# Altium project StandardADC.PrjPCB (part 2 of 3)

## Sheet StdADC05.SchDoc
size B
Used 2 times, as channels FPGA1, FPGA2. Parts and nets are listed once, with the designators drawn on the sheet.
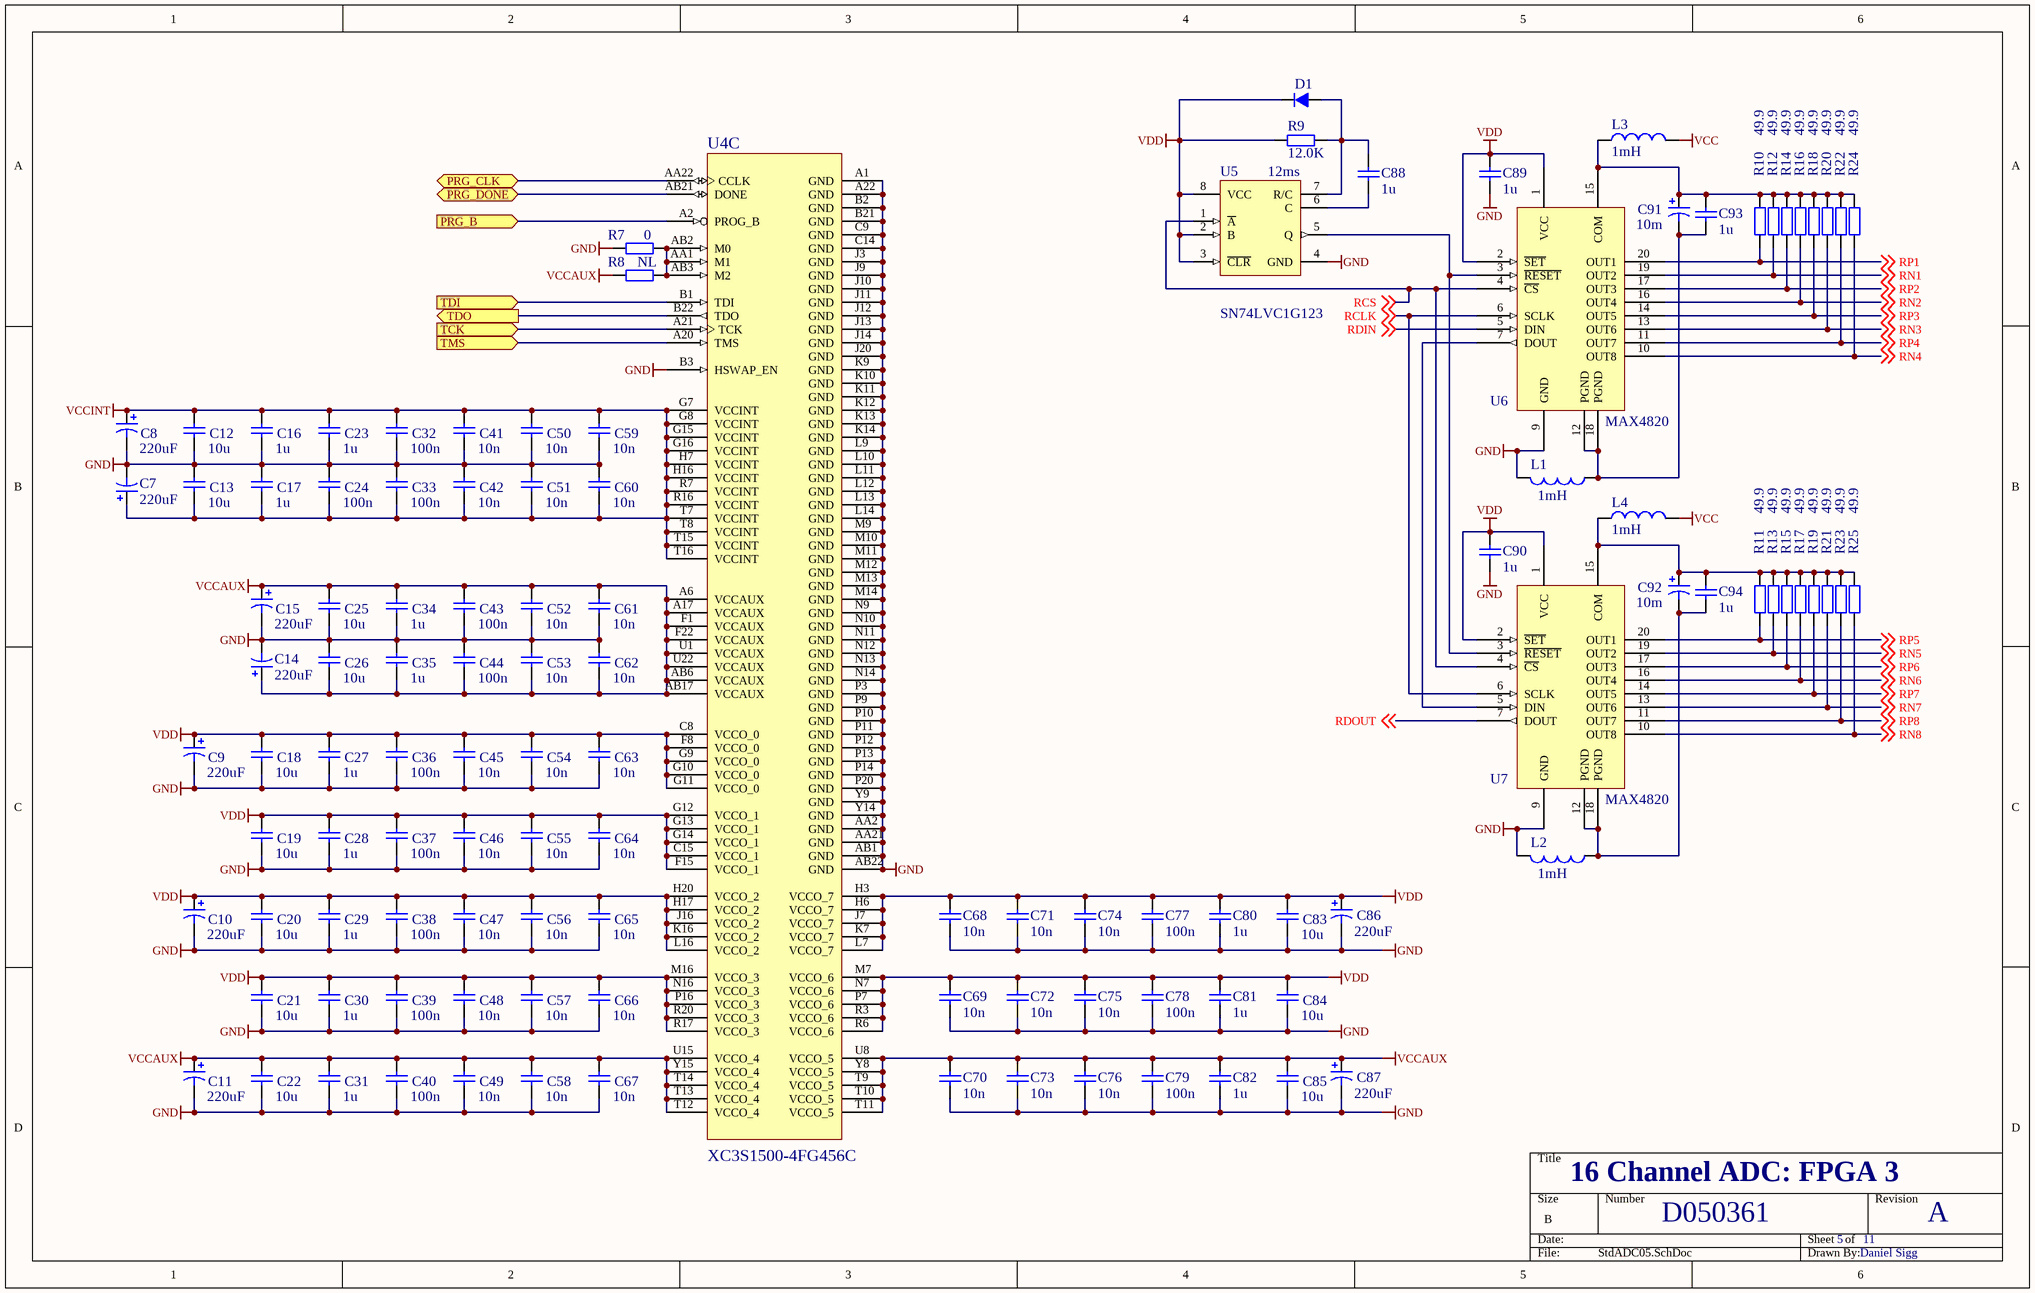
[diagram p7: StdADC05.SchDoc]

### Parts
C7  220uF  [D]
C8  220uF  [D]
C9  220uF  [D]
C10  220uF  [D]
C11  220uF  [D]
C12  value 10u  [CC2012-0805]  (hidden comment: Cap)
C13  value 10u  [CC2012-0805]  (hidden comment: Cap)
C14  220uF  [D]
C15  220uF  [D]
C16  value 1u  [CC1608-0603]  (hidden comment: Cap)
C17  value 1u  [CC1608-0603]  (hidden comment: Cap)
C18  value 10u  [CC2012-0805]  (hidden comment: Cap)
C19  value 10u  [CC2012-0805]  (hidden comment: Cap)
C20  value 10u  [CC2012-0805]  (hidden comment: Cap)
C21  value 10u  [CC2012-0805]  (hidden comment: Cap)
C22  value 10u  [CC2012-0805]  (hidden comment: Cap)
C23  value 1u  [CC1608-0603]  (hidden comment: Cap)
C24  value 100n  [CC1608-0603]  (hidden comment: Cap)
C25  value 10u  [CC2012-0805]  (hidden comment: Cap)
C26  value 10u  [CC2012-0805]  (hidden comment: Cap)
C27  value 1u  [CC1608-0603]  (hidden comment: Cap)
C28  value 1u  [CC1608-0603]  (hidden comment: Cap)
C29  value 1u  [CC1608-0603]  (hidden comment: Cap)
C30  value 1u  [CC1608-0603]  (hidden comment: Cap)
C31  value 1u  [CC1608-0603]  (hidden comment: Cap)
C32  value 100n  [CC1608-0603]  (hidden comment: Cap)
C33  value 100n  [CC1608-0603]  (hidden comment: Cap)
C34  value 1u  [CC1608-0603]  (hidden comment: Cap)
C35  value 1u  [CC1608-0603]  (hidden comment: Cap)
C36  value 100n  [CC1608-0603]  (hidden comment: Cap)
C37  value 100n  [CC1608-0603]  (hidden comment: Cap)
C38  value 100n  [CC1608-0603]  (hidden comment: Cap)
C39  value 100n  [CC1608-0603]  (hidden comment: Cap)
C40  value 100n  [CC1608-0603]  (hidden comment: Cap)
C41  value 10n  [CC1005-0402]  (hidden comment: Cap)
C42  value 10n  [CC1005-0402]  (hidden comment: Cap)
C43  value 100n  [CC1608-0603]  (hidden comment: Cap)
C44  value 100n  [CC1608-0603]  (hidden comment: Cap)
C45  value 10n  [CC1005-0402]  (hidden comment: Cap)
C46  value 10n  [CC1005-0402]  (hidden comment: Cap)
C47  value 10n  [CC1005-0402]  (hidden comment: Cap)
C48  value 10n  [CC1005-0402]  (hidden comment: Cap)
C49  value 10n  [CC1005-0402]  (hidden comment: Cap)
C50  value 10n  [CC1005-0402]  (hidden comment: Cap)
C51  value 10n  [CC1005-0402]  (hidden comment: Cap)
C52  value 10n  [CC1005-0402]  (hidden comment: Cap)
C53  value 10n  [CC1005-0402]  (hidden comment: Cap)
C54  value 10n  [CC1005-0402]  (hidden comment: Cap)
C55  value 10n  [CC1005-0402]  (hidden comment: Cap)
C56  value 10n  [CC1005-0402]  (hidden comment: Cap)
C57  value 10n  [CC1005-0402]  (hidden comment: Cap)
C58  value 10n  [CC1005-0402]  (hidden comment: Cap)
C59  value 10n  [CC1005-0402]  (hidden comment: Cap)
C60  value 10n  [CC1005-0402]  (hidden comment: Cap)
C61  value 10n  [CC1005-0402]  (hidden comment: Cap)
C62  value 10n  [CC1005-0402]  (hidden comment: Cap)
C63  value 10n  [CC1005-0402]  (hidden comment: Cap)
C64  value 10n  [CC1005-0402]  (hidden comment: Cap)
C65  value 10n  [CC1005-0402]  (hidden comment: Cap)
C66  value 10n  [CC1005-0402]  (hidden comment: Cap)
C67  value 10n  [CC1005-0402]  (hidden comment: Cap)
C68  value 10n  [CC1005-0402]  (hidden comment: Cap)
C69  value 10n  [CC1005-0402]  (hidden comment: Cap)
C70  value 10n  [CC1005-0402]  (hidden comment: Cap)
C71  value 10n  [CC1005-0402]  (hidden comment: Cap)
C72  value 10n  [CC1005-0402]  (hidden comment: Cap)
C73  value 10n  [CC1005-0402]  (hidden comment: Cap)
C74  value 10n  [CC1005-0402]  (hidden comment: Cap)
C75  value 10n  [CC1005-0402]  (hidden comment: Cap)
C76  value 10n  [CC1005-0402]  (hidden comment: Cap)
C77  value 100n  [CC1608-0603]  (hidden comment: Cap)
C78  value 100n  [CC1608-0603]  (hidden comment: Cap)
C79  value 100n  [CC1608-0603]  (hidden comment: Cap)
C80  value 1u  [CC1608-0603]  (hidden comment: Cap)
C81  value 1u  [CC1608-0603]  (hidden comment: Cap)
C82  value 1u  [CC1608-0603]  (hidden comment: Cap)
C83  value 10u  [CC2012-0805]  (hidden comment: Cap)
C84  value 10u  [CC2012-0805]  (hidden comment: Cap)
C85  value 10u  [CC2012-0805]  (hidden comment: Cap)
C86  220uF  [D]
C87  220uF  [D]
C88  value 1u  [CC1608-0603]  (hidden comment: Cap)
C89  value 1u  [CC1608-0603]  (hidden comment: Cap)
C90  value 1u  [CC1608-0603]  (hidden comment: Cap)
C91  10m  [RB7.6-15]
C92  10m  [RB7.6-15]
C93  value 1u  [CC1608-0603]  (hidden comment: Cap)
C94  value 1u  [CC1608-0603]  (hidden comment: Cap)
D1  diode  [SO-G3/C2.25]  (value not drawn)
L1  1mH  [CC4532-1812]
L2  1mH  [CC4532-1812]
L3  1mH  [CC4532-1812]
L4  1mH  [CC4532-1812]
R7  0  [CR2012-0805]
R8  NL  [CR2012-0805]
R9  12.0K  [CR2012-0805]
R10  49.9  [CR2012-0805]
R11  49.9  [CR2012-0805]
R12  49.9  [CR2012-0805]
R13  49.9  [CR2012-0805]
R14  49.9  [CR2012-0805]
R15  49.9  [CR2012-0805]
R16  49.9  [CR2012-0805]
R17  49.9  [CR2012-0805]
R18  49.9  [CR2012-0805]
R19  49.9  [CR2012-0805]
R20  49.9  [CR2012-0805]
R21  49.9  [CR2012-0805]
R22  49.9  [CR2012-0805]
R23  49.9  [CR2012-0805]
R24  49.9  [CR2012-0805]
R25  49.9  [CR2012-0805]
U4  XC3S1500-4FG456C  [FG456]  (part C of 3)
U5  SN74LVC1G123  Pulse width: 12ms  [SSO-G8/SM8]
U6  MAX4820  [TSSOP20]
U7  MAX4820  [TSSOP20]

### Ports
PRG_B (in), PRG_CLK (bidir), PRG_DONE (bidir), TCK (in), TDI (in), TDO (out), TMS (in)

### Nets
GND: C7.2 C8.2 C9.2 C10.2 C11.2 C12.2 C13.1 C14.2 C15.2 C16.2 C17.1 C18.2 C19.2 C20.2 C21.2 C22.2 C23.2 C24.1 C25.2 C26.1 C27.2 C28.2 C29.2 C30.2 C31.2 C32.2 C33.1 C34.2 C35.1 C36.2 C37.2 C38.2 C39.2 C40.2 C41.2 C42.1 C43.2 C44.1 C45.2 C46.2 C47.2 C48.2 C49.2 C50.2 C51.1 C52.2 C53.1 C54.2 C55.2 C56.2 C57.2 C58.2 C59.2 C60.1 C61.2 C62.1 C63.2 C64.2 C65.2 C66.2 C67.2 C68.2 C69.2 C70.2 C71.2 C72.2 C73.2 C74.2 C75.2 C76.2 C77.2 C78.2 C79.2 C80.2 C81.2 C82.2 C83.2 C84.2 C85.2 C86.2 C87.2 C89.1 C90.1 L1.2 L2.2 R7.2 U4.A1(GND) U4.A22(GND) U4.AA2(GND) U4.AA21(GND) U4.AB1(GND) U4.AB22(GND) U4.B2(GND) U4.B3(HSWAP_EN) U4.B21(GND) U4.C9(GND) U4.C14(GND) U4.J3(GND) U4.J9(GND) U4.J10(GND) U4.J11(GND) U4.J12(GND) U4.J13(GND) U4.J14(GND) U4.J20(GND) U4.K9(GND) U4.K10(GND) U4.K11(GND) U4.K12(GND) U4.K13(GND) U4.K14(GND) U4.L9(GND) U4.L10(GND) U4.L11(GND) U4.L12(GND) U4.L13(GND) U4.L14(GND) U4.M9(GND) U4.M10(GND) U4.M11(GND) U4.M12(GND) U4.M13(GND) U4.M14(GND) U4.N9(GND) U4.N10(GND) U4.N11(GND) U4.N12(GND) U4.N13(GND) U4.N14(GND) U4.P3(GND) U4.P9(GND) U4.P10(GND) U4.P11(GND) U4.P12(GND) U4.P13(GND) U4.P14(GND) U4.P20(GND) U4.Y9(GND) U4.Y14(GND) U5.4(GND) U6.9(GND) U7.9(GND)
VCC: L3.2 L4.2
VCCAUX: C11.1 C14.1 C15.1 C22.1 C25.1 C26.2 C31.1 C34.1 C35.2 C40.1 C43.1 C44.2 C49.1 C52.1 C53.2 C58.1 C61.1 C62.2 C67.1 C70.1 C73.1 C76.1 C79.1 C82.1 C85.1 C87.1 R8.2 U4.A6(VCCAUX) U4.A17(VCCAUX) U4.AB6(VCCAUX) U4.AB17(VCCAUX) U4.F1(VCCAUX) U4.F22(VCCAUX) U4.T9(VCCO_5) U4.T10(VCCO_5) U4.T11(VCCO_5) U4.T12(VCCO_4) U4.T13(VCCO_4) U4.T14(VCCO_4) U4.U1(VCCAUX) U4.U8(VCCO_5) U4.U15(VCCO_4) U4.U22(VCCAUX) U4.Y8(VCCO_5) U4.Y15(VCCO_4)
VCCINT: C7.1 C8.1 C12.1 C13.2 C16.1 C17.2 C23.1 C24.2 C32.1 C33.2 C41.1 C42.2 C50.1 C51.2 C59.1 C60.2 U4.G7(VCCINT) U4.G8(VCCINT) U4.G15(VCCINT) U4.G16(VCCINT) U4.H7(VCCINT) U4.H16(VCCINT) U4.R7(VCCINT) U4.R16(VCCINT) U4.T7(VCCINT) U4.T8(VCCINT) U4.T15(VCCINT) U4.T16(VCCINT)
VDD: C9.1 C10.1 C18.1 C19.1 C20.1 C21.1 C27.1 C28.1 C29.1 C30.1 C36.1 C37.1 C38.1 C39.1 C45.1 C46.1 C47.1 C48.1 C54.1 C55.1 C56.1 C57.1 C63.1 C64.1 C65.1 C66.1 C68.1 C69.1 C71.1 C72.1 C74.1 C75.1 C77.1 C78.1 C80.1 C81.1 C83.1 C84.1 C86.1 C89.2 C90.2 D1.3(K) R9.1 U4.C8(VCCO_0) U4.C15(VCCO_1) U4.F8(VCCO_0) U4.F15(VCCO_1) U4.G9(VCCO_0) U4.G10(VCCO_0) U4.G11(VCCO_0) U4.G12(VCCO_1) U4.G13(VCCO_1) U4.G14(VCCO_1) U4.H3(VCCO_7) U4.H6(VCCO_7) U4.H17(VCCO_2) U4.H20(VCCO_2) U4.J7(VCCO_7) U4.J16(VCCO_2) U4.K7(VCCO_7) U4.K16(VCCO_2) U4.L7(VCCO_7) U4.L16(VCCO_2) U4.M7(VCCO_6) U4.M16(VCCO_3) U4.N7(VCCO_6) U4.N16(VCCO_3) U4.P7(VCCO_6) U4.P16(VCCO_3) U4.R3(VCCO_6) U4.R6(VCCO_6) U4.R17(VCCO_3) U4.R20(VCCO_3) U5.2(B) U5.3(~{CLR}) U5.8(VCC) U6.1(VCC) U6.2(~{SET}) U7.1(VCC) U7.2(~{SET})
PRG_B: U4.A2(PROG_B) ; port PRG_B
PRG_CLK: U4.AA22(CCLK) ; port PRG_CLK
PRG_DONE: U4.AB21(DONE) ; port PRG_DONE
RCLK: U6.6(SCLK) U7.6(SCLK) ; off-sheet RCLK
RCS: U5.1(~{A}) U6.4(~{CS}) U7.4(~{CS}) ; off-sheet RCS
RDIN: U6.5(DIN) ; off-sheet RDIN
RDOUT: U7.7(DOUT) ; off-sheet RDOUT
RN1: R12.2 U6.19(OUT2) ; off-sheet RN1
RN2: R16.2 U6.16(OUT4) ; off-sheet RN2
RN3: R20.2 U6.13(OUT6) ; off-sheet RN3
RN4: R24.2 U6.10(OUT8) ; off-sheet RN4
RN5: R13.2 U7.19(OUT2) ; off-sheet RN5
RN6: R17.2 U7.16(OUT4) ; off-sheet RN6
RN7: R21.2 U7.13(OUT6) ; off-sheet RN7
RN8: R25.2 U7.10(OUT8) ; off-sheet RN8
RP1: R10.2 U6.20(OUT1) ; off-sheet RP1
RP2: R14.2 U6.17(OUT3) ; off-sheet RP2
RP3: R18.2 U6.14(OUT5) ; off-sheet RP3
RP4: R22.2 U6.11(OUT7) ; off-sheet RP4
RP5: R11.2 U7.20(OUT1) ; off-sheet RP5
RP6: R15.2 U7.17(OUT3) ; off-sheet RP6
RP7: R19.2 U7.14(OUT5) ; off-sheet RP7
RP8: R23.2 U7.11(OUT7) ; off-sheet RP8
TCK: U4.A21(TCK) ; port TCK
TDI: U4.B1(TDI) ; port TDI
TDO: U4.B22(TDO) ; port TDO
TMS: U4.A20(TMS) ; port TMS
NetC88_1: C88.1 U5.6(C)
NetC88_2: C88.2 D1.1(A) R9.2 U5.7(R/C)
NetC91_1: C91.1 C93.2 L3.1 R10.1 R12.1 R14.1 R16.1 R18.1 R20.1 R22.1 R24.1 U6.15(COM)
NetC91_2: C91.2 C93.1 L1.1 U6.12(PGND) U6.18(PGND)
NetC92_1: C92.1 C94.2 L4.1 R11.1 R13.1 R15.1 R17.1 R19.1 R21.1 R23.1 R25.1 U7.15(COM)
NetC92_2: C92.2 C94.1 L2.1 U7.12(PGND) U7.18(PGND)
NetR7_1: R7.1 R8.1 U4.AA1(M1) U4.AB2(M0) U4.AB3(M2)
NetU5_5: U5.5(Q) U6.3(~{RESET}) U7.3(~{RESET})
NetU6_7: U6.7(DOUT) U7.5(DIN)

Not connected (* = marked no-connect by the designer): D1 2; U6 8(NC); U7 8(NC)

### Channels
FPGA1: designators C7=C7A C8=C8A C9=C9A C10=C10A C11=C11A C12=C12A C13=C13A C14=C14A C15=C15A C16=C16A C17=C17A C18=C18A C19=C19A C20=C20A C21=C21A C22=C22A C23=C23A C24=C24A C25=C25A C26=C26A C27=C27A C28=C28A C29=C29A C30=C30A C31=C31A C32=C32A C33=C33A C34=C34A C35=C35A C36=C36A C37=C37A C38=C38A C39=C39A C40=C40A C41=C41A C42=C42A C43=C43A C44=C44A C45=C45A C46=C46A C47=C47A C48=C48A C49=C49A C50=C50A C51=C51A C52=C52A C53=C53A C54=C54A C55=C55A C56=C56A C57=C57A C58=C58A C59=C59A C60=C60A C61=C61A C62=C62A C63=C63A C64=C64A C65=C65A C66=C66A C67=C67A C68=C68A C69=C69A C70=C70A C71=C71A C72=C72A C73=C73A C74=C74A C75=C75A C76=C76A C77=C77A C78=C78A C79=C79A C80=C80A C81=C81A C82=C82A C83=C83A C84=C84A C85=C85A C86=C86A C87=C87A C88=C88A C89=C89A C90=C90A C91=C91A C92=C92A C93=C93A C94=C94A D1=D1A L1=L1A L2=L2A L3=L3A L4=L4A R7=R7A R8=R8A R9=R9A R10=R10A R11=R11A R12=R12A R13=R13A R14=R14A R15=R15A R16=R16A R17=R17A R18=R18A R19=R19A R20=R20A R21=R21A R22=R22A R23=R23A R24=R24A R25=R25A U4=U4A#3 U5=U5A U6=U6A U7=U7A; ports PRG_B=NetU4A#3_A2 PRG_CLK=NetU4A#3_AA22 PRG_DONE=NetU4A#3_AB21 TCK=NetU4A#3_A21 TDI=NetU4A#3_B1 TDO=NetU4A#3_B22 TMS=NetU4A#3_A20
FPGA2: designators C7=C7B C8=C8B C9=C9B C10=C10B C11=C11B C12=C12B C13=C13B C14=C14B C15=C15B C16=C16B C17=C17B C18=C18B C19=C19B C20=C20B C21=C21B C22=C22B C23=C23B C24=C24B C25=C25B C26=C26B C27=C27B C28=C28B C29=C29B C30=C30B C31=C31B C32=C32B C33=C33B C34=C34B C35=C35B C36=C36B C37=C37B C38=C38B C39=C39B C40=C40B C41=C41B C42=C42B C43=C43B C44=C44B C45=C45B C46=C46B C47=C47B C48=C48B C49=C49B C50=C50B C51=C51B C52=C52B C53=C53B C54=C54B C55=C55B C56=C56B C57=C57B C58=C58B C59=C59B C60=C60B C61=C61B C62=C62B C63=C63B C64=C64B C65=C65B C66=C66B C67=C67B C68=C68B C69=C69B C70=C70B C71=C71B C72=C72B C73=C73B C74=C74B C75=C75B C76=C76B C77=C77B C78=C78B C79=C79B C80=C80B C81=C81B C82=C82B C83=C83B C84=C84B C85=C85B C86=C86B C87=C87B C88=C88B C89=C89B C90=C90B C91=C91B C92=C92B C93=C93B C94=C94B D1=D1B L1=L1B L2=L2B L3=L3B L4=L4B R7=R7B R8=R8B R9=R9B R10=R10B R11=R11B R12=R12B R13=R13B R14=R14B R15=R15B R16=R16B R17=R17B R18=R18B R19=R19B R20=R20B R21=R21B R22=R22B R23=R23B R24=R24B R25=R25B U4=U4B#3 U5=U5B U6=U6B U7=U7B; ports PRG_B=NetU4A#3_A2 PRG_CLK=NetU4A#3_AA22 PRG_DONE=NetU4A#3_AB21 TCK=NetU4A#3_A21 TDI=NetU4A#3_B22 TDO=NetU4B#3_B22 TMS=NetU4A#3_A20

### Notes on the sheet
- 16 Channel ADC: FPGA 3
- D050361
- 5
- 11
- A
- Daniel Sigg

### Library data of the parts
C7-C11 C14 C15 C86 C87 = T494D: Solid Tantalum Chip Capacitor, Standard T494 Series - Low ESR, Industrial Grade; Part Number: PCE3603CT-ND
C12 C13 C16-C85 C88-C90 C93 C94 = Cap: Capacitor; Manufacturer: Generic Components; Part Number: 399-1254-1-ND; Class I: Passive
C91 C92 = Cap Pol1: Polarized Capacitor (Radial)
D1 = DIODE_SOT23: Single diode in SOT23 package; Part Number: BAT400D-FDICT-ND
L1-L4 = Inductor: Code_IEC: 1005
R7 R8 = Res2: Resistor
R9-R25 = Res2: Resistor; Tolerance: 1%
U4 = XC3S1500-4FG456C: Spartan-3 1.2V FPGA, 333 User I/Os, 456-ball FBGA, Standard Performance, Commercial Grade; PackageDocument: ver1.1, Apr-2001
U5 = SN74LVC1G123: Single retriggerable monostable multivibrator
U6 U7 = MAX4820: 8 channel relay driver, serial interface

## Sheet StdADC10.SchDoc
size B
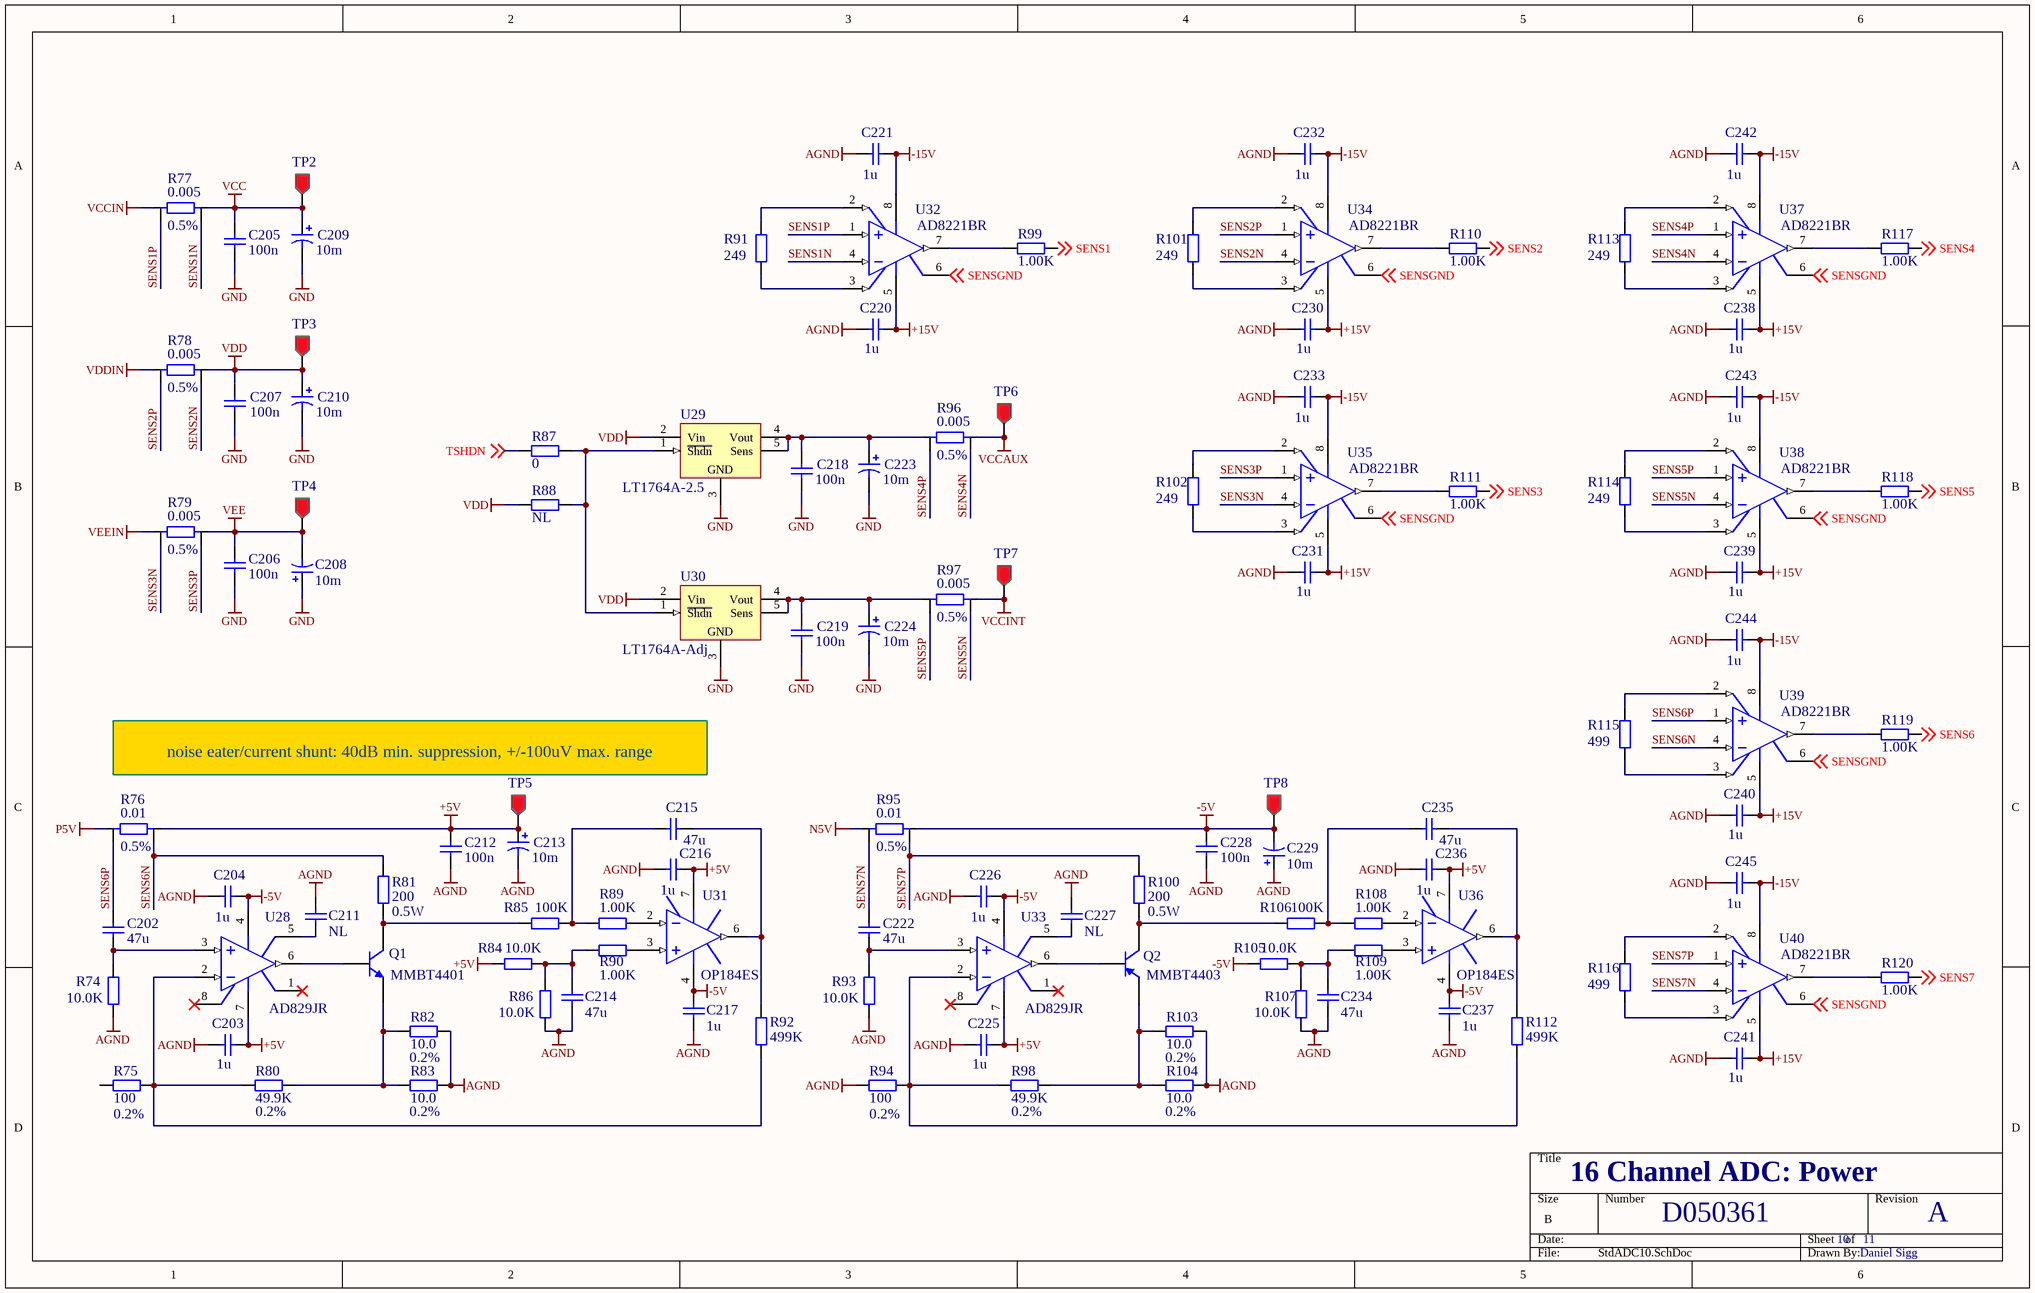
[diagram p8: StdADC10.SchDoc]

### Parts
C202  47u  [CC3225-1210]
C203  1u  [CC2012-0805]
C204  1u  [CC2012-0805]
C205  100n  [CC2012-0805]
C206  100n  [CC2012-0805]
C207  100n  [CC2012-0805]
C208  10m  [RB7.6-15]
C209  10m  [RB7.6-15]
C210  10m  [RB7.6-15]
C211  NL  [CC2012-0805]
C212  100n  [CC1005-0402]
C213  10m  [RB7.6-15]
C214  47u  [CC3225-1210]
C215  47u  [CC3225-1210]
C216  1u  [CC2012-0805]
C217  1u  [CC2012-0805]
C218  100n  [CC2012-0805]
C219  100n  [CC2012-0805]
C220  1u  [CC2012-0805]
C221  1u  [CC2012-0805]
C222  47u  [CC3225-1210]
C223  10m  [RB7.6-15]
C224  10m  [RB7.6-15]
C225  1u  [CC2012-0805]
C226  1u  [CC2012-0805]
C227  NL  [CC2012-0805]
C228  100n  [CC1005-0402]
C229  10m  [RB7.6-15]
C230  1u  [CC2012-0805]
C231  1u  [CC2012-0805]
C232  1u  [CC2012-0805]
C233  1u  [CC2012-0805]
C234  47u  [CC3225-1210]
C235  47u  [CC3225-1210]
C236  1u  [CC2012-0805]
C237  1u  [CC2012-0805]
C238  1u  [CC2012-0805]
C239  1u  [CC2012-0805]
C240  1u  [CC2012-0805]
C241  1u  [CC2012-0805]
C242  1u  [CC2012-0805]
C243  1u  [CC2012-0805]
C244  1u  [CC2012-0805]
C245  1u  [CC2012-0805]
Q1  MMBT4401  [SOT-23A]
Q2  MMBT4403  [SOT-23A]
R74  10.0K  [CR2012-0805]
R75  Tolerance: 0.2%  [CR2012-0805]  (hidden comment: 100)
R76  Tolerance: 0.5%  [RW10862-4325]  (hidden comment: 0.01)
R77  Tolerance: 0.5%  [RW10862-4325]  (hidden comment: 0.005)
R78  Tolerance: 0.5%  [RW10862-4325]  (hidden comment: 0.005)
R79  Tolerance: 0.5%  [RW10862-4325]  (hidden comment: 0.005)
R80  Tolerance: 0.2%  [CR2012-0805]  (hidden comment: 49.9K)
R81  Power: 0.5W  [CR5025-2010]  (hidden comment: 200)
R82  Tolerance: 0.2%  [CR2012-0805]  (hidden comment: 10.0)
R83  Tolerance: 0.2%  [CR2012-0805]  (hidden comment: 10.0)
R84  10.0K  [CR2012-0805]
R85  100K  [CR2012-0805]
R86  10.0K  [CR2012-0805]
R87  0  [CR2012-0805]
R88  NL  [CR2012-0805]
R89  1.00K  [CR2012-0805]
R90  1.00K  [CR2012-0805]
R91  249  [CR2012-0805]
R92  499K  [CR2012-0805]
R93  10.0K  [CR2012-0805]
R94  Tolerance: 0.2%  [CR2012-0805]  (hidden comment: 100)
R95  Tolerance: 0.5%  [RW10862-4325]  (hidden comment: 0.01)
R96  Tolerance: 0.5%  [RW10862-4325]  (hidden comment: 0.005)
R97  Tolerance: 0.5%  [RW10862-4325]  (hidden comment: 0.005)
R98  Tolerance: 0.2%  [CR2012-0805]  (hidden comment: 49.9K)
R99  1.00K  [CR2012-0805]
R100  Power: 0.5W  [CR5025-2010]  (hidden comment: 200)
R101  249  [CR2012-0805]
R102  249  [CR2012-0805]
R103  Tolerance: 0.2%  [CR2012-0805]  (hidden comment: 10.0)
R104  Tolerance: 0.2%  [CR2012-0805]  (hidden comment: 10.0)
R105  10.0K  [CR2012-0805]
R106  100K  [CR2012-0805]
R107  10.0K  [CR2012-0805]
R108  1.00K  [CR2012-0805]
R109  1.00K  [CR2012-0805]
R110  1.00K  [CR2012-0805]
R111  1.00K  [CR2012-0805]
R112  499K  [CR2012-0805]
R113  249  [CR2012-0805]
R114  249  [CR2012-0805]
R115  499  [CR2012-0805]
R116  499  [CR2012-0805]
R117  1.00K  [CR2012-0805]
R118  1.00K  [CR2012-0805]
R119  1.00K  [CR2012-0805]
R120  1.00K  [CR2012-0805]
TP2  Testpoint  [TP1]  (value not drawn)
TP3  Testpoint  [TP1]  (value not drawn)
TP4  Testpoint  [TP1]  (value not drawn)
TP5  Testpoint  [TP1]  (value not drawn)
TP6  Testpoint  [TP1]  (value not drawn)
TP7  Testpoint  [TP1]  (value not drawn)
TP8  Testpoint  [TP1]  (value not drawn)
U28  AD829JR  [R-8D]
U29  LT1764A-2.5  [TO-220-5B]
U30  LT1764A-Adj  [TO-220-5B]
U31  OP184ES  [R-8D]
U32  AD8221BR  [SO-G8]
U33  AD829JR  [R-8D]
U34  AD8221BR  [SO-G8]
U35  AD8221BR  [SO-G8]
U36  OP184ES  [R-8D]
U37  AD8221BR  [SO-G8]
U38  AD8221BR  [SO-G8]
U39  AD8221BR  [SO-G8]
U40  AD8221BR  [SO-G8]

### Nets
+5V: C203.1 C212.1 C213.1 C216.1 C225.1 C236.1 R76.4 R84.1 TP5.1 U28.7(V+) U31.7(V+) U33.7(V+) U36.7(V+)
+15V: C220.1 C230.1 C231.1 C238.1 C239.1 C240.1 C241.1 U32.5(V-) U34.5(V-) U35.5(V-) U37.5(V-) U38.5(V-) U39.5(V-) U40.5(V-)
-5V: C204.1 C217.1 C226.1 C228.1 C229.2 C237.1 R95.4 R105.1 TP8.1 U28.4(V-) U31.4(V-) U33.4(V-) U36.4(V-)
-15V: C221.1 C232.1 C233.1 C242.1 C243.1 C244.1 C245.1 U32.8(V+) U34.8(V+) U35.8(V+) U37.8(V+) U38.8(V+) U39.8(V+) U40.8(V+)
AGND: C203.2 C204.2 C211.2 C212.2 C213.2 C214.1 C216.2 C217.2 C220.2 C221.2 C225.2 C226.2 C227.2 C228.2 C229.1 C230.2 C231.2 C232.2 C233.2 C234.1 C236.2 C237.2 C238.2 C239.2 C240.2 C241.2 C242.2 C243.2 C244.2 C245.2 R74.2 R82.1 R83.1 R86.1 R93.2 R94.1 R103.1 R104.1 R107.1
GND: C205.2 C206.2 C207.2 C208.1 C209.2 C210.2 C218.2 C219.2 C223.2 C224.2 U29.3(GND) U30.3(GND)
N5V: R95.1
P5V: R76.1
VCC: C205.1 C209.1 R77.4 TP2.1
VCCAUX: R96.4 TP6.1
VCCIN: R77.1
VCCINT: R97.4 TP7.1
VDD: C207.1 C210.1 R78.4 R88.1 TP3.1 U29.2(Vin) U30.2(Vin)
VDDIN: R78.1
VEE: C206.1 C208.2 R79.4 TP4.1
VEEIN: R79.1
SENS1: R99.2 ; off-sheet SENS1
SENS1N: R77.3 U32.4(IN-)
SENS1P: R77.2 U32.1(IN+)
SENS2: R110.2 ; off-sheet SENS2
SENS2N: R78.3 U34.4(IN-)
SENS2P: R78.2 U34.1(IN+)
SENS3: R111.2 ; off-sheet SENS3
SENS3N: R79.2 U35.4(IN-)
SENS3P: R79.3 U35.1(IN+)
SENS4: R117.2 ; off-sheet SENS4
SENS4N: R96.3 U37.4(IN-)
SENS4P: R96.2 U37.1(IN+)
SENS5: R118.2 ; off-sheet SENS5
SENS5N: R97.3 U38.4(IN-)
SENS5P: R97.2 U38.1(IN+)
SENS6: R119.2 ; off-sheet SENS6
SENS6N: R76.3 R81.2 U39.4(IN-)
SENS6P: C202.1 R76.2 U39.1(IN+)
SENS7: R120.2 ; off-sheet SENS7
SENS7N: C222.1 R95.2 U40.4(IN-)
SENS7P: R95.3 R100.2 U40.1(IN+)
SENSGND: U32.6(REF) U34.6(REF) U35.6(REF) U37.6(REF) U38.6(REF) U39.6(REF) U40.6(REF) ; off-sheet SENSGND
TSHDN: R87.1 ; off-sheet TSHDN
NetC202_2: C202.2 R74.1 U28.3(IN+)
NetC211_1: C211.1 U28.5(C_COMP)
NetC214_2: C214.2 R84.2 R86.2 R90.1
NetC215_1: C215.1 R85.2 R89.1
NetC215_2: C215.2 R92.1 U31.6(OUT)
NetC218_1: C218.1 C223.1 R96.1 U29.4(Vout) U29.5(Sens)
NetC219_1: C219.1 C224.1 R97.1 U30.4(Vout) U30.5(Sens)
NetC222_2: C222.2 R93.1 U33.3(IN+)
NetC227_1: C227.1 U33.5(C_COMP)
NetC234_2: C234.2 R105.2 R107.2 R109.1
NetC235_1: C235.1 R106.2 R108.1
NetC235_2: C235.2 R112.1 U36.6(OUT)
NetQ1_1: Q1.1(B) U28.6(OUT)
NetQ1_2: Q1.2(E) R80.1 R82.2 R83.2
NetQ1_3: Q1.3(C) R81.1 R85.1
NetQ2_1: Q2.1(B) U33.6(OUT)
NetQ2_2: Q2.2(E) R98.1 R103.2 R104.2
NetQ2_3: Q2.3(C) R100.1 R106.1
NetR75_2: R75.2 R80.2 R92.2 U28.2(IN-)
NetR87_2: R87.2 R88.2 U29.1(~{Shdn}) U30.1(~{Shdn})
NetR89_2: R89.2 U31.2(IN-)
NetR90_2: R90.2 U31.3(IN+)
NetR91_1: R91.1 U32.2(RG)
NetR91_2: R91.2 U32.3(RG)
NetR94_2: R94.2 R98.2 R112.2 U33.2(IN-)
NetR99_1: R99.1 U32.7(OUT)
NetR101_1: R101.1 U34.2(RG)
NetR101_2: R101.2 U34.3(RG)
NetR102_1: R102.1 U35.2(RG)
NetR102_2: R102.2 U35.3(RG)
NetR108_2: R108.2 U36.2(IN-)
NetR109_2: R109.2 U36.3(IN+)
NetR110_1: R110.1 U34.7(OUT)
NetR111_1: R111.1 U35.7(OUT)
NetR113_1: R113.1 U37.2(RG)
NetR113_2: R113.2 U37.3(RG)
NetR114_1: R114.1 U38.2(RG)
NetR114_2: R114.2 U38.3(RG)
NetR115_1: R115.1 U39.2(RG)
NetR115_2: R115.2 U39.3(RG)
NetR116_1: R116.1 U40.2(RG)
NetR116_2: R116.2 U40.3(RG)
NetR117_1: R117.1 U37.7(OUT)
NetR118_1: R118.1 U38.7(OUT)
NetR119_1: R119.1 U39.7(OUT)
NetR120_1: R120.1 U40.7(OUT)

Not connected (* = marked no-connect by the designer): R75 1; U28 1(OS_NUL)* 8(OS_NUL)*; U31 1(OS_NUL) 5(C_COMP) 8(OS_NUL); U33 1(OS_NUL)* 8(OS_NUL)*; U36 1(OS_NUL) 5(C_COMP) 8(OS_NUL)

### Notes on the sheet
- noise eater/current shunt: 40dB min. suppression, +/-100uV max. range
- 16 Channel ADC: Power
- D050361
- 10
- 11
- A
- Daniel Sigg

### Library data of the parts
C202-C207 C211 C212 C214-C222 C225-C228 C230-C245 = Cap Semi: Capacitor (Semiconductor SIM Model)
C208-C210 C213 C223 C224 C229 = Cap Pol1: Polarized Capacitor (Radial)
Q1 = BC817-40: NPN General Purpose Amplifier
Q2 = BC807-40: PNP General Purpose Amplifier
R74 R81-R93 R99-R120 = Res2: Resistor; Tolerance: 1%
R75 R80 R94 R98 = Res2: Resistor
R76-R79 R95-R97 = RW1S0CK: Four-Terminal Current Sense Resistor
TP2-TP8 = TP_POSITIVE
U28 U31 U33 U36 = AD829JR: High-Speed, Low-Noise Video Operational Amplifier; PackageDocument: 1998
U29 U30 = LT1764A: 5 Terminal positive LDO regulator
U32 U34 U35 U37-U40 = AD8221: Precision Instrumentation Amplifier

## Sheet StdADC11.SchDoc
size B
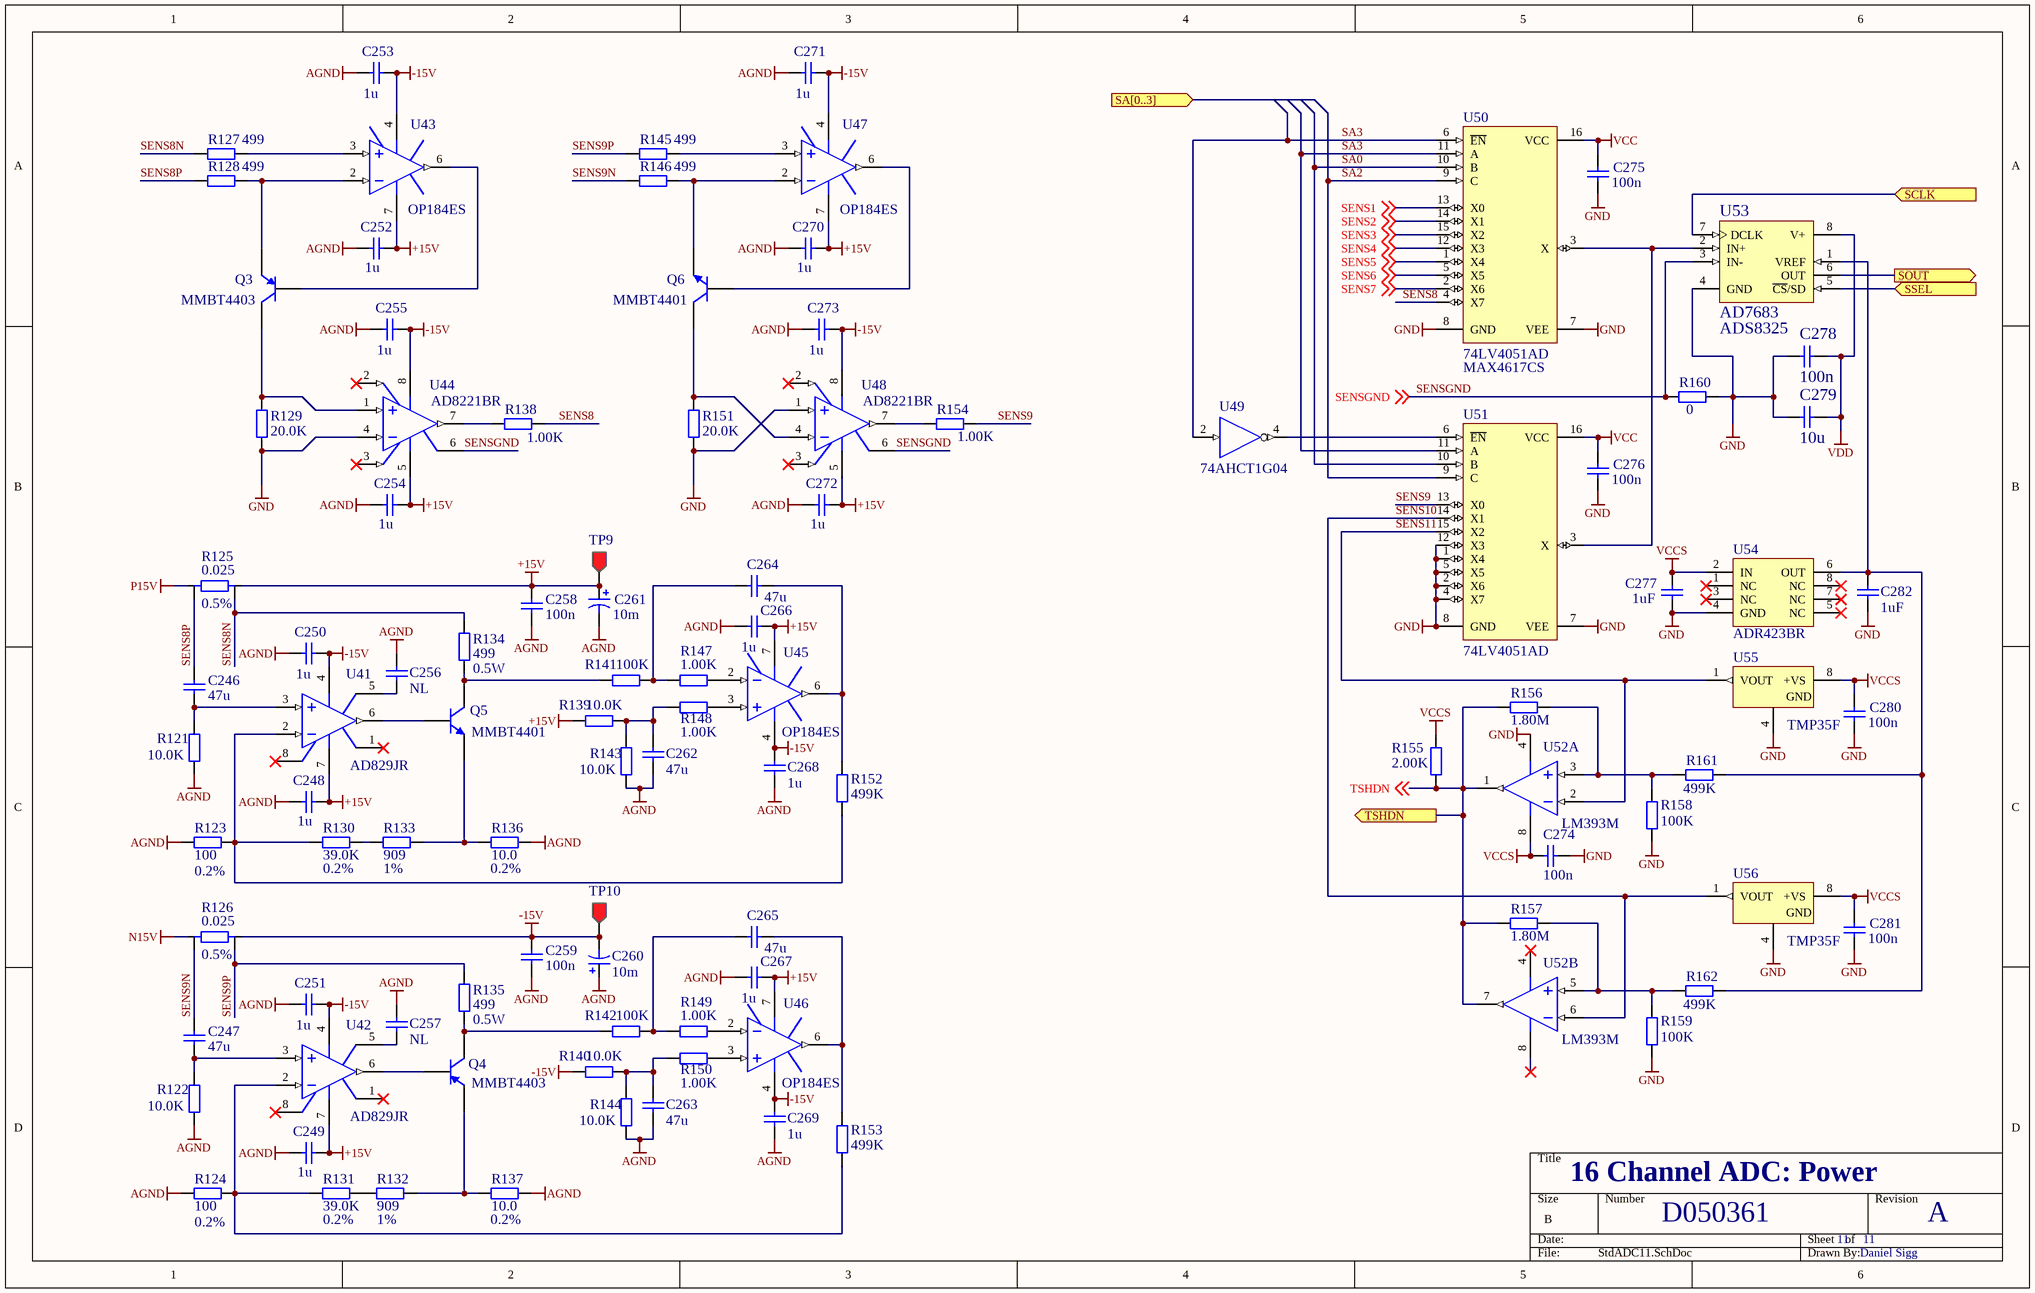
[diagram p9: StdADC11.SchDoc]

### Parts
C246  47u  [CC3225-1210]
C247  47u  [CC3225-1210]
C248  1u  [CC2012-0805]
C249  1u  [CC2012-0805]
C250  1u  [CC2012-0805]
C251  1u  [CC2012-0805]
C252  1u  [CC2012-0805]
C253  1u  [CC2012-0805]
C254  1u  [CC2012-0805]
C255  1u  [CC2012-0805]
C256  NL  [CC2012-0805]
C257  NL  [CC2012-0805]
C258  100n  [CC1005-0402]
C259  100n  [CC1005-0402]
C260  10m  [RB7.6-15]
C261  10m  [RB7.6-15]
C262  47u  [CC3225-1210]
C263  47u  [CC3225-1210]
C264  47u  [CC3225-1210]
C265  47u  [CC3225-1210]
C266  1u  [CC2012-0805]
C267  1u  [CC2012-0805]
C268  1u  [CC2012-0805]
C269  1u  [CC2012-0805]
C270  1u  [CC2012-0805]
C271  1u  [CC2012-0805]
C272  1u  [CC2012-0805]
C273  1u  [CC2012-0805]
C274  100n  [CC2012-0805]
C275  100n  [CC2012-0805]
C276  100n  [CC2012-0805]
C277  1uF  [CC2012-0805]
C278  value 100n  [C3216-1206]  (hidden comment: Cap)
C279  value 10u  [C3216-1206]  (hidden comment: Cap)
C280  100n  [CC2012-0805]
C281  100n  [CC2012-0805]
C282  1uF  [CC2012-0805]
Q3  MMBT4403  [SOT-23A]
Q4  MMBT4403  [SOT-23A]
Q5  MMBT4401  [SOT-23A]
Q6  MMBT4401  [SOT-23A]
R121  10.0K  [CR2012-0805]
R122  10.0K  [CR2012-0805]
R123  Tolerance: 0.2%  [CR2012-0805]  (hidden comment: 100)
R124  Tolerance: 0.2%  [CR2012-0805]  (hidden comment: 100)
R125  Tolerance: 0.5%  [RW10862-4325]  (hidden comment: 0.025)
R126  Tolerance: 0.5%  [RW10862-4325]  (hidden comment: 0.025)
R127  499  [CR2012-0805]
R128  499  [CR2012-0805]
R129  20.0K  [CR2012-0805]
R130  Tolerance: 0.2%  [CR2012-0805]  (hidden comment: 39.0K)
R131  Tolerance: 0.2%  [CR2012-0805]  (hidden comment: 39.0K)
R132  Tolerance: 1%  [CR2012-0805]  (hidden comment: 909)
R133  Tolerance: 1%  [CR2012-0805]  (hidden comment: 909)
R134  Power: 0.5W  [CR5025-2010]  (hidden comment: 499)
R135  Power: 0.5W  [CR5025-2010]  (hidden comment: 499)
R136  Tolerance: 0.2%  [CR2012-0805]  (hidden comment: 10.0)
R137  Tolerance: 0.2%  [CR2012-0805]  (hidden comment: 10.0)
R138  1.00K  [CR2012-0805]
R139  10.0K  [CR2012-0805]
R140  10.0K  [CR2012-0805]
R141  100K  [CR2012-0805]
R142  100K  [CR2012-0805]
R143  10.0K  [CR2012-0805]
R144  10.0K  [CR2012-0805]
R145  499  [CR2012-0805]
R146  499  [CR2012-0805]
R147  1.00K  [CR2012-0805]
R148  1.00K  [CR2012-0805]
R149  1.00K  [CR2012-0805]
R150  1.00K  [CR2012-0805]
R151  20.0K  [CR2012-0805]
R152  499K  [CR2012-0805]
R153  499K  [CR2012-0805]
R154  1.00K  [CR2012-0805]
R155  2.00K  [CR2012-0805]
R156  1.80M  [CR2012-0805]
R157  1.80M  [CR2012-0805]
R158  100K  [CR2012-0805]
R159  100K  [CR2012-0805]
R160  0  [CR2012-0805]
R161  499K  [CR2012-0805]
R162  499K  [CR2012-0805]
TP9  Testpoint  [TP1]  (value not drawn)
TP10  Testpoint  [TP1]  (value not drawn)
U41  AD829JR  [R-8D]
U42  AD829JR  [R-8D]
U43  OP184ES  [SO-8]
U44  AD8221BR  [SO-G8]
U45  OP184ES  [R-8D]
U46  OP184ES  [R-8D]
U47  OP184ES  [SO-8]
U48  AD8221BR  [SO-G8]
U49  74AHCT1G04  [SO-G5/E2.4]
U50  74LV4051AD  Alternative: MAX4617CS  [M16A]
U51  74LV4051AD  [M16A]
U52  LM393M  [M08A]  (parts A,B of 2)
U53  AD7683  Alternative: ADS8325  [182H]
U54  ADR423BR  [R-8]
U55  TMP35F  [M08A]
U56  TMP35F  [M08A]

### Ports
SA[0..3] (in), SCLK (in), SOUT (out), SSEL (in), TSHDN (out)

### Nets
+15V: C248.1 C249.1 C252.1 C254.1 C258.1 C261.1 C266.1 C267.1 C270.1 C272.1 R125.4 R139.1 TP9.1 U41.7(V+) U42.7(V+) U43.7(V+) U44.5(V-) U45.7(V+) U46.7(V+) U47.7(V+) U48.5(V-)
-15V: C250.1 C251.1 C253.1 C255.1 C259.1 C260.2 C268.1 C269.1 C271.1 C273.1 R126.4 R140.1 TP10.1 U41.4(V-) U42.4(V-) U43.4(V-) U44.8(V+) U45.4(V-) U46.4(V-) U47.4(V-) U48.8(V+)
AGND: C248.2 C249.2 C250.2 C251.2 C252.2 C253.2 C254.2 C255.2 C256.2 C257.2 C258.2 C259.2 C260.1 C261.2 C262.1 C263.1 C266.2 C267.2 C268.2 C269.2 C270.2 C271.2 C272.2 C273.2 R121.2 R122.2 R123.1 R124.1 R136.1 R137.1 R143.1 R144.1
GND: C274.1 C275.2 C276.2 C277.1 C278.1 C279.1 C280.2 C281.2 C282.1 R129.1 R151.1 R158.2 R159.2 R160.2 U44.4(IN-) U48.1(IN+) U49.3(GND) U50.7(VEE) U50.8(GND) U51.1(X4) U51.2(X6) U51.4(X7) U51.5(X5) U51.7(VEE) U51.8(GND) U51.12(X3) U52.4(GND) U53.4(GND) U54.4(GND) U55.4(GND) U56.4(GND)
N15V: R126.1
P15V: R125.1
VCC: C275.1 C276.1 U49.5(VCC) U50.16(VCC) U51.16(VCC)
VCCS: C274.2 C277.2 C280.1 C281.1 R155.1 U52.8(V+) U54.2(IN) U55.8(+VS) U56.8(+VS)
VDD: C278.2 C279.2 U53.8(V+)
SA0: U50.10(B) U51.10(B)
SA2: U50.9(C) U51.9(C)
SA3: U49.2(A) U50.6(~{EN}) U50.11(A) U51.11(A)
SENS1: U50.13(X0) ; off-sheet SENS1
SENS2: U50.14(X1) ; off-sheet SENS2
SENS3: U50.15(X2) ; off-sheet SENS3
SENS4: U50.12(X3) ; off-sheet SENS4
SENS5: U50.1(X4) ; off-sheet SENS5
SENS6: U50.5(X5) ; off-sheet SENS6
SENS7: U50.2(X6) ; off-sheet SENS7
SENS8: R138.2 U50.4(X7)
SENS8N: R125.3 R127.2 R134.2
SENS8P: C246.1 R125.2 R128.2
SENS9: R154.2 U51.13(X0)
SENS9N: C247.1 R126.2 R146.2
SENS9P: R126.3 R135.2 R145.2
SENS10: U51.14(X1) U52.6(IN-) U56.1(VOUT)
SENS11: U51.15(X2) U52.2(IN-) U55.1(VOUT)
SENSGND: R160.1 U44.6(REF) U48.6(REF) U53.3(IN-) ; off-sheet SENSGND
TSHDN: R155.2 R156.2 R157.2 U52.1(OUT) U52.7(OUT) ; off-sheet TSHDN, port TSHDN
NetC246_2: C246.2 R121.1 U41.3(IN+)
NetC247_2: C247.2 R122.1 U42.3(IN+)
NetC256_1: C256.1 U41.5(C_COMP)
NetC257_1: C257.1 U42.5(C_COMP)
NetC262_2: C262.2 R139.2 R143.2 R148.1
NetC263_2: C263.2 R140.2 R144.2 R150.1
NetC264_1: C264.1 R141.2 R147.1
NetC264_2: C264.2 R152.1 U45.6(OUT)
NetC265_1: C265.1 R142.2 R149.1
NetC265_2: C265.2 R153.1 U46.6(OUT)
NetC282_2: C282.2 R161.1 R162.1 U53.1(VREF) U54.6(OUT)
NetQ3_1: Q3.1(B) U43.6(OUT)
NetQ3_2: Q3.2(E) R128.1 U43.2(IN-)
NetQ3_3: Q3.3(C) R129.2 U44.1(IN+)
NetQ4_1: Q4.1(B) U42.6(OUT)
NetQ4_2: Q4.2(E) R132.1 R137.2
NetQ4_3: Q4.3(C) R135.1 R142.1
NetQ5_1: Q5.1(B) U41.6(OUT)
NetQ5_2: Q5.2(E) R133.1 R136.2
NetQ5_3: Q5.3(C) R134.1 R141.1
NetQ6_1: Q6.1(B) U47.6(OUT)
NetQ6_2: Q6.2(E) R146.1 U47.2(IN-)
NetQ6_3: Q6.3(C) R151.2 U48.4(IN-)
NetR123_2: R123.2 R130.2 R152.2 U41.2(IN-)
NetR124_2: R124.2 R131.2 R153.2 U42.2(IN-)
NetR127_1: R127.1 U43.3(IN+)
NetR130_1: R130.1 R133.2
NetR131_1: R131.1 R132.2
NetR138_1: R138.1 U44.7(OUT)
NetR145_1: R145.1 U47.3(IN+)
NetR147_2: R147.2 U45.2(IN-)
NetR148_2: R148.2 U45.3(IN+)
NetR149_2: R149.2 U46.2(IN-)
NetR150_2: R150.2 U46.3(IN+)
NetR154_1: R154.1 U48.7(OUT)
NetR156_1: R156.1 R158.1 R161.2 U52.3(IN+)
NetR157_1: R157.1 R159.1 R162.2 U52.5(IN+)
NetU49_4: U49.4(Y) U51.6(~{EN})
NetU50_3: U50.3(X) U51.3(X) U53.2(IN+)
NetU53_5: U53.5(~{CS}/SD) ; port SSEL
NetU53_6: U53.6(OUT) ; port SOUT
NetU53_7: U53.7(DCLK) ; port SCLK

Not connected (* = marked no-connect by the designer): U41 1(OS_NUL)* 8(OS_NUL)*; U42 1(OS_NUL)* 8(OS_NUL)*; U43 1(NUL) 5(NUL) 8(NC); U44 2(RG)* 3(RG)*; U45 1(OS_NUL) 5(C_COMP) 8(OS_NUL); U46 1(OS_NUL) 5(C_COMP) 8(OS_NUL); U47 1(NUL) 5(NUL) 8(NC); U48 2(RG)* 3(RG)*; U49 1(NC); U54 1(NC)* 3(NC)* 5(NC)* 7(NC)* 8(NC)*

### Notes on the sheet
- 16 Channel ADC: Power
- D050361
- 11
- A
- Daniel Sigg

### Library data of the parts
C246-C259 C262-C277 C280-C282 = Cap Semi: Capacitor (Semiconductor SIM Model)
C260 C261 = Cap Pol1: Polarized Capacitor (Radial)
C278 C279 = Cap: Capacitor; Manufacturer: Generic Components; Part Number: 399-1250-1-ND; Class I: Passive
Q3 Q4 = BC807-40: PNP General Purpose Amplifier
Q5 Q6 = BC817-40: NPN General Purpose Amplifier
R121 R122 R127-R129 R134-R162 = Res2: Resistor; Tolerance: 1%
R123 R124 R130-R133 = Res2: Resistor
R125 R126 = RW1S0CK: Four-Terminal Current Sense Resistor
TP9 TP10 = TP_POSITIVE
U41 U42 U45 U46 = AD829JR: as U28 on sheet StdADC10
U43 U47 = OP184ES: Precision Rail-to-Rail Input and Ouput Operational Amplifier; PackageDocument: revA; Note: Pin 8 is not connected.
U44 U48 = AD8221: Precision Instrumentation Amplifier
U49 = SN74LVC1G04: Single hex inverter
U50 U51 = MM74HC4051M: 8-Channel Analog Multiplexer; PackageDocument: 2000
U52 = LM393M: Low-Power Low Offset Voltage Dual Comparator
U53 = ADS7822UC: 12-Bit High-Speed 2.7V Micro Power Sampling Analog-to-Digital Converter
U54 = ADR292ER: Low-Noise Micropower Precision Voltage Reference; Note: Pins 1, 3, 5, 7 and 8 are not connected
U55 U56 = LM35DM: Precision CentigradeTemperature Sensor; Note: Pins 2,3,5,6 and 7 are NC and not drawn

## Sheet StdADC08.SchDoc
size B
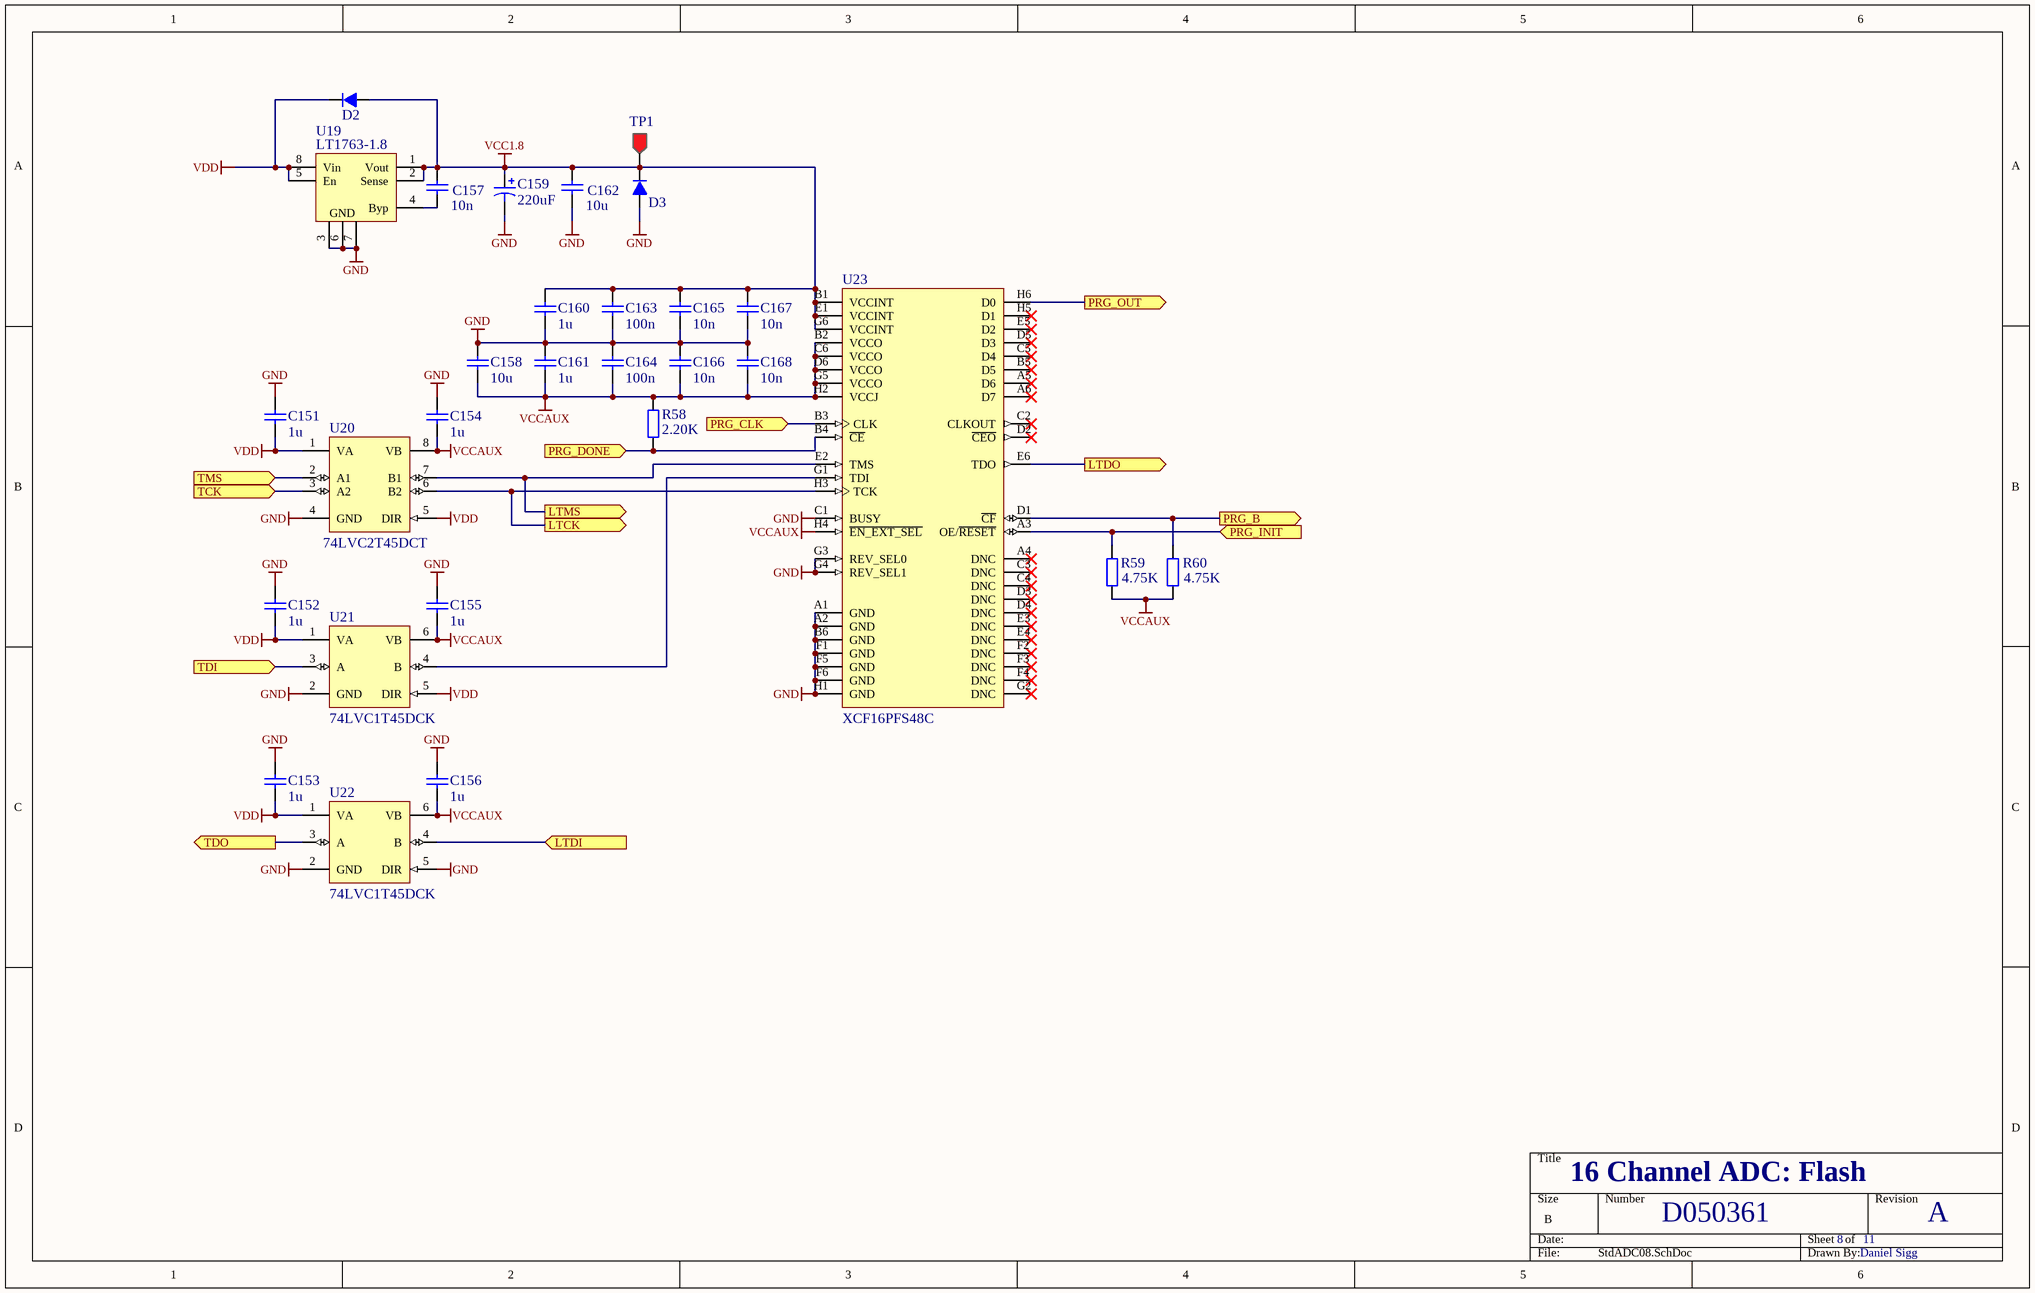
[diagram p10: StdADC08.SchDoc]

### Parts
C151  value 1u  [CC2012-0805]  (hidden comment: Cap)
C152  value 1u  [CC2012-0805]  (hidden comment: Cap)
C153  value 1u  [CC2012-0805]  (hidden comment: Cap)
C154  value 1u  [CC2012-0805]  (hidden comment: Cap)
C155  value 1u  [CC2012-0805]  (hidden comment: Cap)
C156  value 1u  [CC2012-0805]  (hidden comment: Cap)
C157  value 10n  [CR3216-1206]  (hidden comment: Cap)
C158  value 10u  [CC2012-0805]  (hidden comment: Cap)
C159  220uF  [D]
C160  value 1u  [CC1608-0603]  (hidden comment: Cap)
C161  value 1u  [CC1608-0603]  (hidden comment: Cap)
C162  value 10u  [CC2012-0805]  (hidden comment: Cap)
C163  value 100n  [CC1608-0603]  (hidden comment: Cap)
C164  value 100n  [CC1608-0603]  (hidden comment: Cap)
C165  value 10n  [CC1005-0402]  (hidden comment: Cap)
C166  value 10n  [CC1005-0402]  (hidden comment: Cap)
C167  value 10n  [CC1005-0402]  (hidden comment: Cap)
C168  value 10n  [CC1005-0402]  (hidden comment: Cap)
D2  diode  [SO-G3/C2.25]  (value not drawn)
D3  diode  [SO-G3/C2.25]  (value not drawn)
R58  2.20K  [CR2012-0805]
R59  4.75K  [CR2012-0805]
R60  4.75K  [CR2012-0805]
TP1  Testpoint  [TP1]  (value not drawn)
U19  LT1763-1.8  [SO-G8]
U20  74LVC2T45DCT  [MSOP8]
U21  74LVC1T45DCK  [SC70]
U22  74LVC1T45DCK  [SC70]
U23  XCF16PFS48C  [FS48]

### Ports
LTCK (out), LTDI (in), LTDO (out), LTMS (out), PRG_B (out), PRG_CLK (in), PRG_DONE (in), PRG_INIT (in), PRG_OUT (out), TCK (in), TDI (in), TDO (out), TMS (in)

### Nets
GND: C151.2 C152.2 C153.2 C154.2 C155.2 C156.2 C158.2 C159.2 C160.1 C161.2 C162.2 C163.1 C164.2 C165.1 C166.2 C167.1 C168.2 D3.1(A) U19.3(GND) U19.6(GND) U19.7(GND) U20.4(GND) U21.2(GND) U22.2(GND) U22.5(DIR) U23.A1(GND) U23.A2(GND) U23.B6(GND) U23.C1(BUSY) U23.F1(GND) U23.F5(GND) U23.F6(GND) U23.G3(REV_SEL0) U23.G4(REV_SEL1) U23.H1(GND)
VCC1.8: C157.1 C159.1 C160.2 C162.1 C163.2 C165.2 C167.2 D2.1(A) D3.3(K) TP1.1 U19.1(Vout) U19.2(Sense) U23.B1(VCCINT) U23.E1(VCCINT) U23.G6(VCCINT)
VCCAUX: C154.1 C155.1 C156.1 C158.1 C161.1 C164.1 C166.1 C168.1 R58.1 R59.2 R60.2 U20.8(VB) U21.6(VB) U22.6(VB) U23.B2(VCCO) U23.C6(VCCO) U23.D6(VCCO) U23.G5(VCCO) U23.H2(VCCJ) U23.H4(~{EN_EXT_SEL})
VDD: C151.1 C152.1 C153.1 D2.3(K) U19.5(En) U19.8(Vin) U20.1(VA) U20.5(DIR) U21.1(VA) U21.5(DIR) U22.1(VA)
NetC157_2: C157.2 U19.4(Byp)
NetR58_2: R58.2 U23.B4(~{CE}) ; port PRG_DONE
NetR59_1: R59.1 U23.A3(OE/~{RESET}) ; port PRG_INIT
NetR60_1: R60.1 U23.D1(~{CF}) ; port PRG_B
NetU20_2: U20.2(A1) ; port TMS
NetU20_3: U20.3(A2) ; port TCK
NetU20_6: U20.6(B2) U23.H3(TCK) ; port LTCK
NetU20_7: U20.7(B1) U23.E2(TMS) ; port LTMS
NetU21_3: U21.3(A) ; port TDI
NetU21_4: U21.4(B) U23.G1(TDI)
NetU22_3: U22.3(A) ; port TDO
NetU22_4: U22.4(B) ; port LTDI
NetU23_B3: U23.B3(CLK) ; port PRG_CLK
NetU23_E6: U23.E6(TDO) ; port LTDO
NetU23_H6: U23.H6(D0) ; port PRG_OUT

Not connected (* = marked no-connect by the designer): D2 2; D3 2; U23 A4(DNC)* A5(D6)* A6(D7)* B5(D5)* C2(CLKOUT)* C3(DNC)* C4(DNC)* C5(D4)* D2(~{CEO})* D3(DNC)* D4(DNC)* D5(D3)* E3(DNC)* E4(DNC)* E5(D2)* F2(DNC)* F3(DNC)* F4(DNC)* G2(DNC)* H5(D1)*

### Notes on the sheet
- 16 Channel ADC: Flash
- D050361
- 8
- 11
- A
- Daniel Sigg

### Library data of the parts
C151-C156 C158 C160-C168 = Cap: as C12 on sheet StdADC05
C157 = Cap: Capacitor; Manufacturer: Generic Components; Part Number: 399-1234-1-ND; Class I: Passive
C159 = T494D: as C7-C11 on sheet StdADC05
D2 D3 = DIODE_SOT23: as D1 on sheet StdADC05
R58-R60 = Res2: Resistor
TP1 = TP_POSITIVE: Part Number: 5005K-ND
U19 = LT1763: Positive voltage regulator; Part Number: LT1763CS8-3.3-ND
U20 = SN74LVC2T45: Dual-Bit Dual Supply Transceiver
U21 U22 = SN74LVC1T45: Single-Bit Dual Supply Transceiver
U23 = XCF16PFS48C: XCF00P Series, Platform Flash In-System Programmable Configuration 1.8V PROM, 48 Ball BGA, 16-Megabit, Commercial Grade; PackageDocument: ver1.0.1, Apr-2005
